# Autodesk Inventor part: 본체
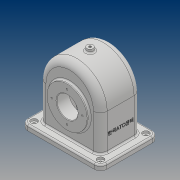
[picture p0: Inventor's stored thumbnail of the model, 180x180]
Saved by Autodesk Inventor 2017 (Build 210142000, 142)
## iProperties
Part Number: 본체
Material: 일반
Document SubType Name: Modeling
Designer: 20
Density: 1 g/cm^3
Appearance: 기본값
Author: 20
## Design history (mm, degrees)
sketch "스케치1"
  geometry: L1 (58, 0)-(58, -78); L2 (58, -78)-(-58, -78); L3 (-58, -78)-(-58, 0); A1 r 58 centre (0, 0) between (58, 0) and (-58, 0); 1 further point
  constraints: 6 end point, 2 point on circle, 2 tangent, 2 vertical, 1 centre point, 1 coincident, 1 horizontal
  dimensions: "d2" = 116 diameter of A1; "d3" = 78 distance from line of L2 point (0, 0)
extrude "돌출1" new body sketch "스케치1" stored distance "d4" = 77; taper "d5" = 0 deg
sketch "스케치2"
  geometry: L1 (52, 0)-(52, -78); L2 (52, -78)-(-52, -78); L3 (-52, -78)-(-52, 0); A1 r 52 centre (0, 0) between (52, 0) and (-52, 0); 1 further point
  constraints: 6 end point, 2 point on circle, 2 tangent, 2 vertical, 1 centre point, 1 coincident, 1 horizontal
  dimensions: "d6" = 104 diameter of A1; "d7" = 78 distance from line of L2 point (0, 0)
extrude "돌출2" cut sketch "스케치2" stored distance "d8" = 67; taper "d9" = 0 deg
sketch "스케치3"
  geometry: L1 (-58, -78)-(58, -78) reference; C1 r 38 at (0, -13); 1 further point
  constraints: 1 centre point, 1 vertical alignment
  dimensions: "d10" = 76 diameter of C1; "d11" = 65 distance from line of L1 C1.centre
extrude "돌출3" join sketch "스케치3" distance "d12" = 5; taper "d13" = 0 deg
sketch "스케치4"
  geometry: L1 (58, 78)-(-58, 78) reference; C1 r 38 at (0, 13); 1 further point
  constraints: 1 centre point, 1 vertical alignment
  dimensions: "d14" = 76 diameter of C1; "d15" = 65 distance from line of L1 C1.centre
extrude "돌출4" join sketch "스케치4" distance "d16" = 10; taper "d17" = 0 deg
sketch "스케치5"
  geometry: L1 (-17, -93.5)-(133, -93.5); L2 (133, -93.5)-(133, 16.5); L3 (133, 16.5)-(-17, 16.5); L4 (-17, 16.5)-(-17, -93.5); L5 (-17, -93.5)-(133, 16.5); L6 (133, -93.5)-(-17, 16.5); L7 (0, 0)-(0, -77) reference; L8 (116, -77)-(0, -77) reference; L9 (0, 0)-(116, 0) reference; L10 (116, 0)-(116, -77) reference; 1 further point
  constraints: 12 end point, 2 midpoint, 2 parallel, 1 horizontal, 1 perpendicular
  dimensions: "d18" = 110 distance of L3.end L1.start; "d19" = 150 distance of L2.end L3.end
extrude "돌출5" join sketch "스케치5" distance "d20" = 10; taper "d21" = 0 deg
node "작업 평면1"
sketch "스케치7"
  geometry: L1 (-52, 78)-(52, 78) reference; C1 r 28 at (0, 13); 1 further point
  constraints: 1 centre point, 1 vertical alignment
  dimensions: "d23" = 56 diameter of C1; "d24" = 65 distance from line of L1 C1.centre
extrude "돌출6" join sketch "스케치7" stored distance "d25" = 14; taper "d26" = 40 deg
sketch "스케치8"
  geometry: C1 r 38 at (0, 0) reference; C2 r 20 at (0, 0); 1 further point
  constraints: 1 centre point, 1 coincident
  dimensions: "d27" = 40 diameter of C2
extrude "돌출7" cut sketch "스케치8" stored distance "d28" = 10; taper "d29" = 0 deg
node "작업 평면2"
sketch "스케치9"
  geometry: C1 r 6 at (75, 55); 1 further point
  constraints: 2 coincident, 1 centre point
  dimensions: "d31" = 12 diameter of C1
extrude "돌출8" join sketch "스케치9" stored distance "d32" = 10; taper "d33" = 5 deg
sketch "스케치10"
  geometry: C1 r 20 at (0, 0) reference; 2 further points
  constraints: 1 vertical alignment
  dimensions: "d34" = 29 distance of point (0, 29) C1.centre
hole "구멍1" sketch "스케치10" at (0, 29) diameter "d35" = 3.242; stored, may be unused: countersink angle "d39" = 90 deg, drill point angle "d41" = 118 deg; dims "d36" = 8, "d37" = 4, "d38" = 2, "d40" = 10
sketch "스케치11"
  geometry: C1 r 28 at (0, 0) reference; 2 further points
  constraints: 1 vertical alignment
  dimensions: "d45" = 29 distance of C1.centre point (0, -29)
hole "구멍2" sketch "스케치11" at (0, -29) diameter "d46" = 3.242; stored, may be unused: countersink angle "d50" = 90 deg, drill point angle "d52" = 118 deg; dims "d47" = 8, "d48" = 4, "d49" = 2, "d51" = 10
fillet "모깎기1" dims "d56" = 12
sketch "스케치12"
  geometry: A1 r 12 centre (-121, -81.5) between (-133, -81.5) and (-121, -93.5) reference; A2 r 12 centre (-121, 4.5) between (-121, 16.5) and (-133, 4.5) reference; A3 r 12 centre (5, 4.5) between (17, 4.5) and (5, 16.5) reference; A4 r 12 centre (5, -81.5) between (5, -93.5) and (17, -81.5) reference; 5 further points
  constraints: 4 coincident
hole "구멍3" sketch "스케치12" at (-121, -81.5), (-121, 4.5), (5, 4.5), (5, -81.5) diameter "d57" = 5; stored, may be unused: countersink angle "d61" = 90 deg, drill point angle "d63" = 118 deg; dims "d58" = 8, "d59" = 12, "d60" = 4, "d62" = 10
fillet "모깎기2" dims "d64" = 13
fillet "모깎기3" dims "d65" = 8
chamfer "모따기1" distance "d66" = 1; stored, may be unused: second distance "d67" = 2, angle "d68" = 45 deg
fillet "모깎기4" dims "d69" = 3
fillet "모깎기5" dims "d70" = 3
hole "구멍4" diameter "d73" = 4.459; stored, may be unused: countersink angle "d77" = 90 deg, drill point angle "d79" = 118 deg; dims "d71" = 10, "d72" = 10, "d74" = 10, "d75" = 12, "d76" = 4, "d78" = 12.8
sketch "스케치13"
  geometry: L1 (0, -13)-(65, -13) reference; L2 (78, 68.5)-(78, -17.5) reference; 2 further points
  constraints: 1 other
  dimensions: "d80" = 38.5 distance from line of L1 point (38, 25.5); "d81" = 40 distance from line of L2 point (38, 25.5)
feature "엠보싱1" sketch "스케치13" dims "d82" = 0.5, "d83" = 0
fillet "모깎기6" dims "d84" = 3
node "솔리드1"
pattern_circular "원형 패턴1" dims angle "d43" = 360 deg
pattern_circular "원형 패턴2" dims angle "d54" = 360 deg
other parameters: "d22" = 14, "d30" = -142
